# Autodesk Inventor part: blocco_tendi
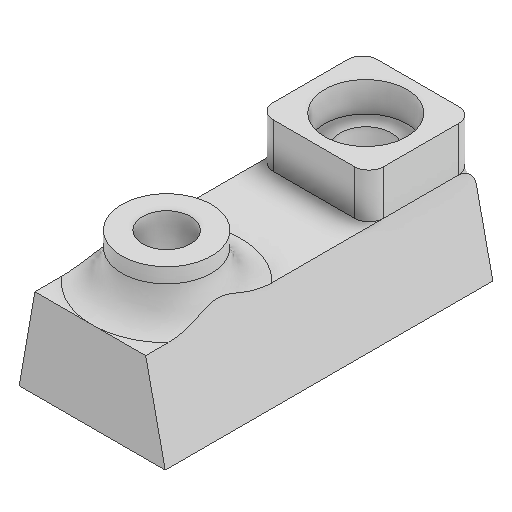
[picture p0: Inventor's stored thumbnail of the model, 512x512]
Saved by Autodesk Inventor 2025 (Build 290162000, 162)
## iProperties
Created: 2025-06
Part Number: blocco_tendi
Material: Generico
Document SubType Name: Modeling
Designer: Ryzen5700u
Density: 1 g/cm^3
Appearance: Default
Author: Ryzen5700u
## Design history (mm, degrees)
sketch "Schizzo1"
  geometry: L1 (-9.261, 2.15)-(-8.203, 8.15) reference; L2 (1.797, -2.23)-(-10.203, -2.23) reference; L3 (-0.203, 8.15)-(0.855, 2.15) reference; L4 (0.855, 2.15)-(-9.261, 2.15) reference; L5 (-8, 7)-(0, 7); L6 (-8.05, 8.15)-(-9.108, 2.15); L7 (-9.108, 2.15)-(0.703, 2.15); L8 (0.703, 2.15)-(-0.611, 8.15); L9 (-0.394, 7.158)-(2.74, 7.287); L10 (2.74, 7.287)-(2.972, -2.085); L11 (2.972, -2.085)-(-11.445, -2.276); L12 (-11.445, -2.276)-(-11.522, 7.3); L13 (-11.522, 7.3)-(-8.2, 7.3); L14 (-10.203, 8.15)-(-8.203, 8.15) reference; L15 (-0.203, 8.15)-(1.797, 8.15) reference; L16 (-8.203, 8.15)-(-0.203, 8.15); L17 (1.797, 8.15)-(1.797, -2.23) reference; L18 (-0.203, 8.15)-(1.797, 8.15) reference; L19 (-10.203, 8.15)-(-8.203, 8.15) reference; L20 (-10.203, -2.23)-(-10.203, 8.15) reference; 2 further points
  constraints: 20 end point, 4 point on line, 2 horizontal
  dimensions: "d0" = 0.15 distance between parallel lines of L1 L6
extrude "Estrusione1" new body sketch "Schizzo1" distance "d1" = 22; taper "d2" = 0 deg
sketch "Schizzo6"
  geometry: C1 r 1.5 at (3.848, 5) reference; 1 further point
extrude "Estrusione5" join sketch "Schizzo6" distance "d23" = 8; taper "d24" = 0 deg
sketch "Schizzo7"
  geometry: C1 r 1.5 at (3.848, 5) reference; C2 r 3 at (3.848, 5); 1 further point
  constraints: 1 centre point, 1 coincident
  dimensions: "d25" = 6 diameter of C2
extrude "Estrusione6" join sketch "Schizzo7" distance "d26" = 3; taper "d27" = 0 deg
fillet "Raccordo2" dims "d28" = 2
sketch "Schizzo8"
  geometry: L1 (0, -13.807)-(0, 0) reference; L2 (7.44, -13.522)-(7.44, 0) reference; L3 (0, 0)-(7.44, 0); L4 (7.44, 0)-(7.44, -7); L5 (7.44, -7)-(0, -7); L6 (0, -7)-(0, 0); 3 further points
  constraints: 8 end point, 2 parallel, 1 horizontal, 1 perpendicular, 1 point on line
  dimensions: "d29" = 7 distance of L3.end L4.end
extrude "Estrusione7" join sketch "Schizzo8" distance "d30" = 3; taper "d31" = 0 deg
sketch "Schizzo9"
  geometry: L1 (0, 0)-(0, -7) reference; L2 (0, -7)-(7.44, -7) reference; L3 (7.44, -7)-(7.44, 0) reference; L4 (7.44, 0)-(0, 0) reference; L5 (0, -13.807)-(0, -7) reference; L6 (0, -7)-(7.44, 0); L7 (0, 0)-(7.44, -7); 2 further points
  constraints: 4 end point, 1 midpoint
  node "Linea chiusa proiettata1"
sketch "Schizzo10"
  geometry: L1 (-0.703, 2.15)-(9.108, 2.15) reference; L2 (4.203, 2.15)-(4.203, 11.15); L3 (5.703, 11.15)-(2.703, 11.15) reference; L4 (1.453, 6.848)-(6.953, 6.848); L5 (6.953, 6.848)-(6.953, 4.448); L6 (6.953, 4.448)-(1.453, 4.448); L7 (1.453, 4.448)-(1.453, 6.848); L8 (1.453, 6.848)-(6.953, 4.448); L9 (6.953, 6.848)-(1.453, 4.448); 2 further points
  constraints: 14 end point, 3 midpoint, 2 parallel, 2 perpendicular, 2 point on line, 1 horizontal
  dimensions: "d39" = 5.5 distance of L5.end L6.end; "d40" = 2.4 distance of L4.end L5.end
extrude "Estrusione8" cut sketch "Schizzo10" stored distance "d41" = 3; taper "d42" = 0 deg
fillet "Raccordo3" dims "d43" = 1
hole "Foro3" sketch "Schizzo9" diameter "d44" = 3.4; stored, may be unused: countersink angle "d48" = 90 deg, drill point angle "d50" = 118 deg; dims "d45" = 6, "d46" = 5.5, "d47" = 2, "d49" = 8
sketch "Schizzo12"
  geometry: C1 r 1.5 at (0, 0); 1 further point
  constraints: 1 centre point
extrude "Estrusione9" cut sketch "Schizzo12" stored distance "d58" = 10; taper "d59" = 0 deg
sketch "Schizzo13"
  geometry: C1 r 3 at (4.906, -5) reference; 1 further point
hole "Foro5" sketch "Schizzo13" at (4.906, -5) diameter "d60" = 3.2; stored, may be unused: countersink angle "d64" = 90 deg, drill point angle "d66" = 118 deg; dims "d61" = 6, "d62" = 11, "d63" = 2.6, "d65" = 8
sketch "Schizzo14"
  geometry: L1 (4.906, -8.175)-(2.156, -6.588); L2 (2.156, -6.588)-(2.156, -3.412); L3 (2.156, -3.412)-(4.906, -1.825); L4 (4.906, -1.825)-(7.656, -3.412); L5 (7.656, -3.412)-(7.656, -6.588); L6 (7.656, -6.588)-(4.906, -8.175); C1 r 1.6 at (4.906, -5) reference; 2 further points
  constraints: 12 end point, 1 coincident, 13 other
  dimensions: "d67" = 5.5 distance between parallel lines of L2 L5
extrude "Estrusione10" cut sketch "Schizzo14" distance "d68" = 3.2; taper "d69" = 0 deg
node "Solido1"
node "Riferimento1"
node "Riferimento2"
node "Riferimento3"
node "Riferimento4"
